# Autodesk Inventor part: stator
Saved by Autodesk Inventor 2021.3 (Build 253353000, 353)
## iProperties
Created: 2021-10
Part Number: stator
Material: Generic
Document SubType Name: Modeling
Designer: Administrator
Density: 1 g/cm^3
Appearance: Default
Title: stator v7
Author: Administrator
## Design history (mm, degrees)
feature "Body1"
body "Solid1"
